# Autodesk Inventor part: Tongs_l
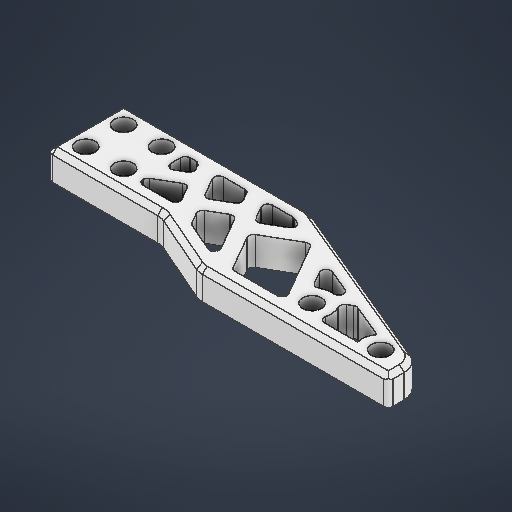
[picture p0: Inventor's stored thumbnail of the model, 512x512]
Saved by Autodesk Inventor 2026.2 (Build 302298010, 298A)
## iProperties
Created: 2026-05
Part Number: Tongs_l
Material: ABS 플라스틱
Document SubType Name: Modeling
Designer: work
Density: 1.06 g/cm^3
Appearance: 매끄러움 - 흰색
Author: work
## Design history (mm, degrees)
sketch "스케치1"
  geometry: L1 (-4, 4)-(4, 4); L2 (4, 4)-(4, -4); L3 (4, -4)-(-4, -4); L4 (-4, -4)-(-4, 4); L5 (-4, 4)-(4, -4); L6 (4, 4)-(-4, -4); L7 (-8, 8)-(8, 8); L8 (8, 8)-(8, -8); L9 (8, -8)-(-8, -8); L10 (-8, -8)-(-8, 8); L11 (-8, 8)-(8, -8); L12 (8, 8)-(-8, -8); L13 (-8, 8)-(-16, 8); L14 (-16, 8)-(-29.748, 14); L15 (-29.748, 14)-(-69.748, 14); L16 (-69.748, 14)-(-69.748, 8); L17 (-69.748, 8)-(-31.398, -8); L18 (-31.398, -8)-(-8, -8); L19 (-8, -5)-(-30.797, -5); L20 (-30.797, -5)-(-66.748, 9.999); L21 (-66.748, 9.999)-(-66.748, 11); L22 (-66.748, 11)-(-30.374, 11); L23 (-30.374, 11)-(-16.626, 5); L24 (-16.626, 5)-(-8, 5); L25 (-48.561, 11)-(-42.029, -0.314); L26 (-45.097, 11)-(-37.465, -2.218); L27 (-30.374, 11)-(-21.136, -5); L28 (-33.838, 11)-(-24.6, -5); L29 (-16.626, 5)-(-10.853, -5); L30 (-21.257, 7.021)-(-14.317, -5); L31 (-37.465, -2.218)-(-29.021, 2.657); L32 (-27.521, 0.059)-(-33.982, -3.671); L33 (-13.739, 0)-(-8, 3.314); L34 (-12.239, -2.598)-(-8, -0.15); L35 (-17.787, 1.011)-(-22.902, -1.942); L36 (-24.402, 0.656)-(-19.287, 3.609); L37 (-46.029, 6.614)-(-51.317, 3.561); L38 (-47.029, 8.346)-(-53.639, 4.53); C1 r 2 at (4, 4); C2 r 2 at (4, -4); C3 r 2 at (-4, -4); C4 r 2 at (-4, 4); 4 further points
  constraints: 76 end point, 24 point on line, 19 parallel, 8 midpoint, 6 perpendicular, 4 centre point, 4 coincident, 3 horizontal, 5 other
  dimensions: "d0" = 8 distance of L2.end L3.end; "d1" = 8 distance of L1.end L2.end; "d2" = 4 diameter of C1; "d3" = 4 diameter of C2; "d4" = 4 diameter of C3; "d5" = 4 diameter of C4; "d6" = 4 distance between parallel lines of L8 L2; "d7" = 8 distance of L7.start L13.end; "d8" = 15 distance of L13.end L14.end; "d9" = 40 distance of L14.end L15.end; "d10" = 6 distance of L15.end L16.end; "d11" = 38.34957 horizontal distance of L16.end L17.end; "d12" = 3 distance between parallel lines of L14 L23; "d13" = 3 distance between parallel lines of L25 L26; "d14" = 3 distance between parallel lines of L28 L27; "d15" = 3 distance between parallel lines of L30 L29; "d16" = 120 deg angle of L22 L28; "d17" = 3 distance between parallel lines of L35 L36; "d18" = 3 distance from line of L31 point (-30.752, -1.806); "d19" = 2 distance between parallel lines of L38 L37; "d20" = 8 distance from line of L25.end L37; "d21" = 3 distance between parallel lines of L34 L33
extrude "돌출1" new body sketch "스케치1" distance "d22" = 6; taper "d23" = 0 deg
sketch "스케치2"
  geometry: L1 (16, -8)-(29.748, -14) reference; L2 (29.748, -14)-(69.748, -14) reference; L3 (69.748, -14)-(69.748, -8) reference; L4 (69.748, -8)-(31.398, 8) reference; L5 (31.398, 8)-(-8, 8) reference; L6 (-8, 8)-(-8, -8) reference; L7 (-8, -8)-(16, -8) reference; L8 (27.521, -0.059)-(24.6, 5) reference; L9 (24.6, 5)-(30.797, 5) reference; L10 (30.797, 5)-(33.982, 3.671) reference; L11 (33.982, 3.671)-(27.521, -0.059) reference; L12 (12.239, 2.598)-(8, 0.15) reference; L13 (8, 0.15)-(8, 5) reference; L14 (8, 5)-(10.853, 5) reference; L15 (10.853, 5)-(12.239, 2.598) reference; L16 (17.787, -1.011)-(14.317, 5) reference; L17 (14.317, 5)-(21.136, 5) reference; L18 (21.136, 5)-(22.902, 1.942) reference; L19 (22.902, 1.942)-(17.787, -1.011) reference; L20 (46.029, -6.614)-(42.029, 0.314) reference; L21 (42.029, 0.314)-(51.317, -3.561) reference; L22 (51.317, -3.561)-(46.029, -6.614) reference; L23 (13.739, 0)-(16.626, -5) reference; L24 (16.626, -5)-(8, -5) reference; L25 (8, -5)-(8, -3.314) reference; L26 (8, -3.314)-(13.739, 0) reference; L27 (19.287, -3.609)-(24.402, -0.656) reference; L28 (24.402, -0.656)-(30.374, -11) reference; L29 (30.374, -11)-(21.257, -7.021) reference; L30 (21.257, -7.021)-(19.287, -3.609) reference; L31 (29.021, -2.657)-(37.465, 2.218) reference; L32 (37.465, 2.218)-(45.097, -11) reference; L33 (45.097, -11)-(33.838, -11) reference; L34 (33.838, -11)-(29.021, -2.657) reference; L35 (47.029, -8.346)-(53.639, -4.53) reference; L36 (53.639, -4.53)-(66.748, -9.999) reference; L37 (66.748, -9.999)-(66.748, -11) reference; L38 (66.748, -11)-(48.561, -11) reference; L39 (48.561, -11)-(47.029, -8.346) reference; C1 r 2 at (4, -4) reference; C2 r 2 at (4, 4) reference; C3 r 2 at (-4, 4) reference; C4 r 2 at (-4, -4) reference; 5 further points
  constraints: 4 coincident
hole "구멍1" sketch "스케치2" at (-4, -4), (4, -4), (4, 4), (-4, 4) diameter "d24" = 4; stored, may be unused: countersink angle "d28" = 90 deg, drill point angle "d30" = 118 deg; dims "d25" = 6, "d26" = 6.2, "d27" = 3, "d29" = 8
fillet "모깎기1" dims "d31" = 1
fillet "모깎기2" dims "d32" = 4
fillet "모깎기3" dims "d33" = 1
chamfer "모따기1" distance "d34" = 1; stored, may be unused: second distance "d35" = 2, angle "d36" = 45 deg
node "작업 평면1"
sketch "스케치3"
  geometry: L1 (39.398, 0)-(0, 0) reference; L2 (0, 0)-(80.713, 0); L3 (80.713, 0)-(80.713, 23.103); L4 (80.713, 23.103)-(0, 23.103); L5 (0, 23.103)-(0, 0); 2 further points
  constraints: 8 end point, 2 parallel, 1 horizontal, 1 perpendicular
extrude "돌출2" cut sketch "스케치3" extent not by distance; stored distance "d38" = 10; taper "d39" = 0 deg
fillet "모깎기4" dims "d40" = 1
fillet "모깎기5" dims "d41" = 4
chamfer "모따기2" distance "d42" = 1; stored, may be unused: second distance "d43" = 2, angle "d44" = 45 deg
sketch "스케치4"
  geometry: L1 (75.288, 13.974)-(40.137, -0.692) reference; L2 (77.748, 21)-(77.748, 17.665) reference; L3 (38.583, 21)-(77.748, 21) reference; L4 (24.765, 15.334)-(36.983, 20.666) reference; L5 (1, 15)-(23.165, 15) reference; L6 (0, 0)-(0, 14) reference; L7 (38.597, -1)-(1, -1) reference; L8 (40.232, 4.339)-(36.387, 6.559) reference; L9 (38.982, 2.077)-(40.117, 2.55) reference; L10 (34.332, 2)-(38.597, 2) reference; L11 (35.021, 6.193)-(33.466, 3.5) reference; L12 (16, 5.117)-(16, 3) reference; L13 (19.373, 4.902)-(17.5, 5.984) reference; L14 (19.141, 2.5)-(19.739, 3.536) reference; L15 (17, 2)-(18.275, 2) reference; L16 (30.036, 5.558)-(26.653, 7.511) reference; L17 (29.425, 2.5)-(30.402, 4.192) reference; L18 (24.049, 2)-(28.559, 2) reference; L19 (25.287, 7.145)-(23.183, 3.5) reference; L20 (57.566, 11.572)-(54.895, 13.114) reference; L21 (52.759, 7.825)-(57.451, 9.783) reference; L22 (53.529, 12.748)-(51.508, 9.248) reference; L23 (16.5, 10.025)-(20.873, 7.5) reference; L24 (16, 11)-(16, 10.891) reference; L25 (22.894, 12)-(17, 12) reference; L26 (22.239, 7.866)-(23.76, 10.5) reference; L27 (29.093, 13.736)-(27.787, 11.475) reference; L28 (35.588, 16.784)-(29.559, 14.153) reference; L29 (32.902, 8.522)-(36.854, 15.368) reference; L30 (28.153, 10.109)-(31.536, 8.156) reference; L31 (51.365, 18)-(42.415, 18) reference; L32 (45.965, 5.648)-(52.231, 16.5) reference; L33 (37.887, 9.157)-(44.599, 5.282) reference; L34 (41.549, 17.5)-(37.521, 10.523) reference; L35 (72.153, 18)-(57.138, 18) reference; L36 (62.095, 11.72)-(72.538, 16.077) reference; L37 (55.895, 14.846)-(61.21, 11.777) reference; L38 (56.272, 17.5)-(55.529, 16.212) reference; C1 r 3.1 at (4, 3) reference; C2 r 3.1 at (4, 11) reference; C3 r 3.1 at (12, 11) reference; C4 r 3.1 at (12, 3) reference; C5 r 2 at (56.395, 15.712); C6 r 4 at (56.395, 15.712); C7 r 4 at (72.153, 17); C8 r 2 at (72.153, 17); A1 r 4 centre (38.597, 3) between (38.597, -1) and (40.137, -0.692) reference; A2 r 4 centre (38.583, 17) between (38.583, 21) and (36.983, 20.666) reference; A3 r 4 centre (23.165, 19) between (23.165, 15) and (24.765, 15.334) reference; A4 r 1 centre (1, 14) between (1, 15) and (0, 14) reference; A5 r 1 centre (1, 0) between (0, 0) and (1, -1) reference; A6 r 1 centre (39.732, 3.473) between (40.117, 2.55) and (40.232, 4.339) reference; A7 r 1 centre (38.597, 3) between (38.597, 2) and (38.982, 2.077) reference; A8 r 1 centre (34.332, 3) between (33.466, 3.5) and (34.332, 2) reference; A9 r 1 centre (35.887, 5.693) between (36.387, 6.559) and (35.021, 6.193) reference; A10 r 1 centre (17, 5.117) between (17.5, 5.984) and (16, 5.117) reference; A11 r 1 centre (18.873, 4.036) between (19.739, 3.536) and (19.373, 4.902) reference; A12 r 1 centre (18.275, 3) between (18.275, 2) and (19.141, 2.5) reference; A13 r 1 centre (17, 3) between (16, 3) and (17, 2) reference; A14 r 1 centre (29.536, 4.692) between (30.402, 4.192) and (30.036, 5.558) reference; A15 r 1 centre (28.559, 3) between (28.559, 2) and (29.425, 2.5) reference; A16 r 1 centre (24.049, 3) between (23.183, 3.5) and (24.049, 2) reference; A17 r 1 centre (26.153, 6.645) between (26.653, 7.511) and (25.287, 7.145) reference; A18 r 1 centre (54.395, 12.248) between (54.895, 13.114) and (53.529, 12.748) reference; A19 r 1 centre (57.066, 10.706) between (57.451, 9.783) and (57.566, 11.572) reference; A20 r 1 centre (52.374, 8.748) between (51.508, 9.248) and (52.759, 7.825) reference; A21 r 1 centre (17, 10.891) between (16, 10.891) and (16.5, 10.025) reference; A22 r 1 centre (17, 11) between (17, 12) and (16, 11) reference; A23 r 1 centre (22.894, 11) between (23.76, 10.5) and (22.894, 12) reference; A24 r 1 centre (21.373, 8.366) between (20.873, 7.5) and (22.239, 7.866) reference; A25 r 1 centre (28.653, 10.975) between (27.787, 11.475) and (28.153, 10.109) reference; A26 r 1 centre (29.959, 13.236) between (29.559, 14.153) and (29.093, 13.736) reference; A27 r 1 centre (35.988, 15.868) between (36.854, 15.368) and (35.588, 16.784) reference; A28 r 1 centre (32.036, 9.022) between (31.536, 8.156) and (32.902, 8.522) reference; A29 r 1 centre (51.365, 17) between (52.231, 16.5) and (51.365, 18) reference; A30 r 1 centre (45.099, 6.148) between (44.599, 5.282) and (45.965, 5.648) reference; A31 r 1 centre (38.387, 10.023) between (37.521, 10.523) and (37.887, 9.157) reference; A32 r 1 centre (42.415, 17) between (42.415, 18) and (41.549, 17.5) reference; A33 r 1 centre (72.153, 17) between (72.538, 16.077) and (72.153, 18) reference; A34 r 1 centre (61.71, 12.643) between (61.21, 11.777) and (62.095, 11.72) reference; A35 r 1 centre (56.395, 15.712) between (55.529, 16.212) and (55.895, 14.846) reference; A36 r 1 centre (57.138, 17) between (57.138, 18) and (56.272, 17.5) reference; A37 r 4 centre (73.748, 17.665) between (75.288, 13.974) and (77.748, 17.665) reference; 11 further points
  constraints: 4 centre point, 4 coincident
  dimensions: "d45" = 4 diameter of C5; "d46" = 8 diameter of C6; "d47" = 8 diameter of C7; "d48" = 4 diameter of C8
  node "투영된 루프2"
extrude "돌출3" join sketch "스케치4" stored distance "d49" = 10; taper "d50" = 0 deg
extrude "돌출4" cut sketch "스케치4" extent not by distance; stored distance "d51" = 10; taper "d52" = 0 deg
fillet "모깎기6" dims "d53" = 1
sketch "스케치5"
  geometry: C1 r 2 at (56.395, 15.712) reference; C2 r 2 at (72.153, 17) reference; 4 further points
  constraints: 2 coincident
hole "구멍2" sketch "스케치5" at (56.395, 15.712), (72.153, 17) diameter "d54" = 4; stored, may be unused: countersink angle "d58" = 90 deg, drill point angle "d60" = 118 deg; dims "d55" = 6, "d56" = 6.2, "d57" = 3, "d59" = 8
fillet "모깎기7" dims "d61" = 1
node "솔리드1"
mirror "미러1"
node "투영된 루프1"
feature "A9D066F2-1C7D-4E18-AEED-F7BC21143FA4" dims "d24" = 4, "d25" = 6, "d26" = 6.2, "d27" = 3, "d28" = 90 deg, "d29" = 8, "d30" = 118 deg
other parameters: "d37" = 0
